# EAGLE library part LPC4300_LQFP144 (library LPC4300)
LQFP144 - SOT486-1 LQFP144: plastic low profile quad flat package; 144 leads; body 20 x 20 x 1.4 mm body + leads 22 x 22 mm Solderland (pads) 0.4 x 1.5 mm on corners (8 x) and 0.28 x 1.5 mm (136 x)
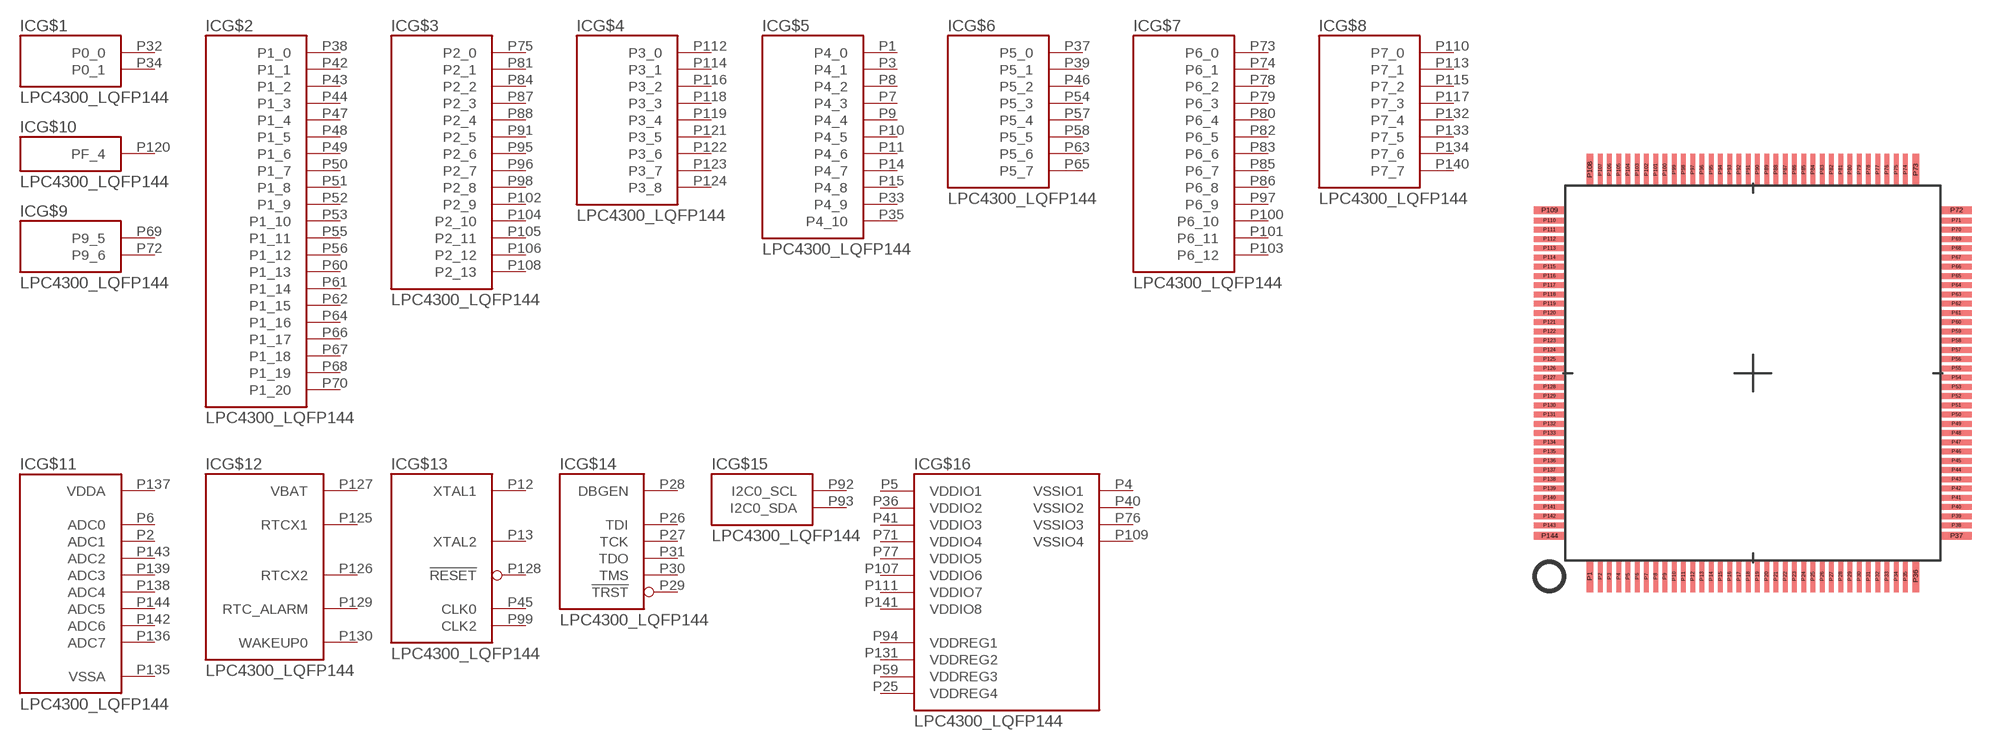
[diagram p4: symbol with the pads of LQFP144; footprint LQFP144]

Designator prefix IC; gates G$1=144_0_PORT0 G$2=144_1_PORT1 G$3=144_2_PORT2 G$4=144_3_PORT3 G$5=144_4_PORT4 G$6=144_5_PORT5 G$7=144_6_PORT6 G$8=144_7_PORT7 G$9=144_9_PORT9 G$10=144_15_PORTF G$11=144_16_ANA G$12=144_17_RTC G$13=144_18_CLK G$14=144_19_DBUG G$15=144_20_I2C G$16=144_21_SUP G$17=144_22_USB

## LPC4300_LQFP144  [LQFP144]
P1  G$5:P4_0
P2  G$11:ADC1  in
P3  G$5:P4_1
P4  G$16:VSSIO1  sup
P5  G$16:VDDIO1  sup
P6  G$11:ADC0  in
P7  G$5:P4_3
P8  G$5:P4_2
P9  G$5:P4_4
P10  G$5:P4_5
P11  G$5:P4_6
P12  G$13:XTAL1  in
P13  G$13:XTAL2  out
P14  G$5:P4_7
P15  G$5:P4_8
P16  G$17:USB0_VDDA3V3_DRIVER
P17  G$17:USB0_VDDA3V3
P18  G$17:USB0_DP
P19  G$17:USB0_VSSA_TERM
P20  G$17:USB0_DM
P21  G$17:USB0_VBUS
P22  G$17:USB0_ID
P23  G$17:USB0_VSSA_REF
P24  G$17:USB0_RREF
P25  G$16:VDDREG4  sup
P26  G$14:TDI
P27  G$14:TCK
P28  G$14:DBGEN  in
P29  G$14:!TRST
P30  G$14:TMS
P31  G$14:TDO
P32  G$1:P0_0
P33  G$5:P4_9
P34  G$1:P0_1
P35  G$5:P4_10
P36  G$16:VDDIO2  sup
P37  G$6:P5_0
P38  G$2:P1_0
P39  G$6:P5_1
P40  G$16:VSSIO2  sup
P41  G$16:VDDIO3  sup
P42  G$2:P1_1
P43  G$2:P1_2
P44  G$2:P1_3
P45  G$13:CLK0  out
P46  G$6:P5_2
P47  G$2:P1_4
P48  G$2:P1_5
P49  G$2:P1_6
P50  G$2:P1_7
P51  G$2:P1_8
P52  G$2:P1_9
P53  G$2:P1_10
P54  G$6:P5_3
P55  G$2:P1_11
P56  G$2:P1_12
P57  G$6:P5_4
P58  G$6:P5_5
P59  G$16:VDDREG3  sup
P60  G$2:P1_13
P61  G$2:P1_14
P62  G$2:P1_15
P63  G$6:P5_6
P64  G$2:P1_16
P65  G$6:P5_7
P66  G$2:P1_17
P67  G$2:P1_18
P68  G$2:P1_19
P69  G$9:P9_5
P70  G$2:P1_20
P71  G$16:VDDIO4  sup
P72  G$9:P9_6
P73  G$7:P6_0
P74  G$7:P6_1
P75  G$3:P2_0
P76  G$16:VSSIO3  sup
P77  G$16:VDDIO5  sup
P78  G$7:P6_2
P79  G$7:P6_3
P80  G$7:P6_4
P81  G$3:P2_1
P82  G$7:P6_5
P83  G$7:P6_6
P84  G$3:P2_2
P85  G$7:P6_7
P86  G$7:P6_8
P87  G$3:P2_3
P88  G$3:P2_4
P89  G$17:USB1_DP
P90  G$17:USB1_DM
P91  G$3:P2_5
P92  G$15:I2C0_SCL
P93  G$15:I2C0_SDA
P94  G$16:VDDREG1  sup
P95  G$3:P2_6
P96  G$3:P2_7
P97  G$7:P6_9
P98  G$3:P2_8
P99  G$13:CLK2  out
P100  G$7:P6_10
P101  G$7:P6_11
P102  G$3:P2_9
P103  G$7:P6_12
P104  G$3:P2_10
P105  G$3:P2_11
P106  G$3:P2_12
P107  G$16:VDDIO6  sup
P108  G$3:P2_13
P109  G$16:VSSIO4  sup
P110  G$8:P7_0
P111  G$16:VDDIO7  sup
P112  G$4:P3_0
P113  G$8:P7_1
P114  G$4:P3_1
P115  G$8:P7_2
P116  G$4:P3_2
P117  G$8:P7_3
P118  G$4:P3_3
P119  G$4:P3_4
P120  G$10:PF_4
P121  G$4:P3_5
P122  G$4:P3_6
P123  G$4:P3_7
P124  G$4:P3_8
P125  G$12:RTCX1  in
P126  G$12:RTCX2  out
P127  G$12:VBAT  pwr
P128  G$13:!RESET  in
P129  G$12:RTC_ALARM  out
P130  G$12:WAKEUP0  in
P131  G$16:VDDREG2  sup
P132  G$8:P7_4
P133  G$8:P7_5
P134  G$8:P7_6
P135  G$11:VSSA  sup
P136  G$11:ADC7  in
P137  G$11:VDDA  sup
P138  G$11:ADC4  in
P139  G$11:ADC3  in
P140  G$8:P7_7
P141  G$16:VDDIO8  sup
P142  G$11:ADC6  in
P143  G$11:ADC2  in
P144  G$11:ADC5  in

## Footprint LQFP144 (pad centres in mm)
LQFP144 - SOT486-1 LQFP144: plastic low profile quad flat package; 144 leads; body 20 x 20 x 1.4 mm body + leads 22 x 22 mm Solderland (pads) 0.4 x 1.5 mm on corners (8 x) and 0.28 x 1.5 mm (136 x)
smd 0.4 x 1.7: P1 -8.81,-11; P36 8.81,-11; P73 8.81,11; P108 -8.81,11
smd 0.28 x 1.7: P2 -8.25,-11; P3 -7.75,-11; P4 -7.25,-11; P5 -6.75,-11; P6 -6.25,-11; P7 -5.75,-11; P8 -5.25,-11; P9 -4.75,-11; P10 -4.25,-11; P11 -3.75,-11; P12 -3.25,-11; P13 -2.75,-11; P14 -2.25,-11; P15 -1.75,-11; P16 -1.25,-11; P17 -0.75,-11; P18 -0.25,-11; P19 0.25,-11; P20 0.75,-11; P21 1.25,-11; P22 1.75,-11; P23 2.25,-11; P24 2.75,-11; P25 3.25,-11; P26 3.75,-11; P27 4.25,-11; P28 4.75,-11; P29 5.25,-11; P30 5.75,-11; P31 6.25,-11; P32 6.75,-11; P33 7.25,-11; P34 7.75,-11; P35 8.25,-11; P74 8.25,11; P75 7.75,11; P76 7.25,11; P77 6.75,11; P78 6.25,11; P79 5.75,11; P80 5.25,11; P81 4.75,11; P82 4.25,11; P83 3.75,11; P84 3.25,11; P85 2.75,11; P86 2.25,11; P87 1.75,11; P88 1.25,11; P89 0.75,11; P90 0.25,11; P91 -0.25,11; P92 -0.75,11; P93 -1.25,11; P94 -1.75,11; P95 -2.25,11; P96 -2.75,11; P97 -3.25,11; P98 -3.75,11; P99 -4.25,11; P100 -4.75,11; P101 -5.25,11; P102 -5.75,11; P103 -6.25,11; P104 -6.75,11; P105 -7.25,11; P106 -7.75,11; P107 -8.25,11
smd 1.7 x 0.4: P37 11,-8.81; P72 11,8.81; P109 -11,8.81; P144 -11,-8.81
smd 1.7 x 0.28: P38 11,-8.25; P39 11,-7.75; P40 11,-7.25; P41 11,-6.75; P42 11,-6.25; P43 11,-5.75; P44 11,-5.25; P45 11,-4.75; P46 11,-4.25; P47 11,-3.75; P48 11,-3.25; P49 11,-2.75; P50 11,-2.25; P51 11,-1.75; P52 11,-1.25; P53 11,-0.75; P54 11,-0.25; P55 11,0.25; P56 11,0.75; P57 11,1.25; P58 11,1.75; P59 11,2.25; P60 11,2.75; P61 11,3.25; P62 11,3.75; P63 11,4.25; P64 11,4.75; P65 11,5.25; P66 11,5.75; P67 11,6.25; P68 11,6.75; P69 11,7.25; P70 11,7.75; P71 11,8.25; P110 -11,8.25; P111 -11,7.75; P112 -11,7.25; P113 -11,6.75; P114 -11,6.25; P115 -11,5.75; P116 -11,5.25; P117 -11,4.75; P118 -11,4.25; P119 -11,3.75; P120 -11,3.25; P121 -11,2.75; P122 -11,2.25; P123 -11,1.75; P124 -11,1.25; P125 -11,0.75; P126 -11,0.25; P127 -11,-0.25; P128 -11,-0.75; P129 -11,-1.25; P130 -11,-1.75; P131 -11,-2.25; P132 -11,-2.75; P133 -11,-3.25; P134 -11,-3.75; P135 -11,-4.25; P136 -11,-4.75; P137 -11,-5.25; P138 -11,-5.75; P139 -11,-6.25; P140 -11,-6.75; P141 -11,-7.25; P142 -11,-7.75; P143 -11,-8.25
